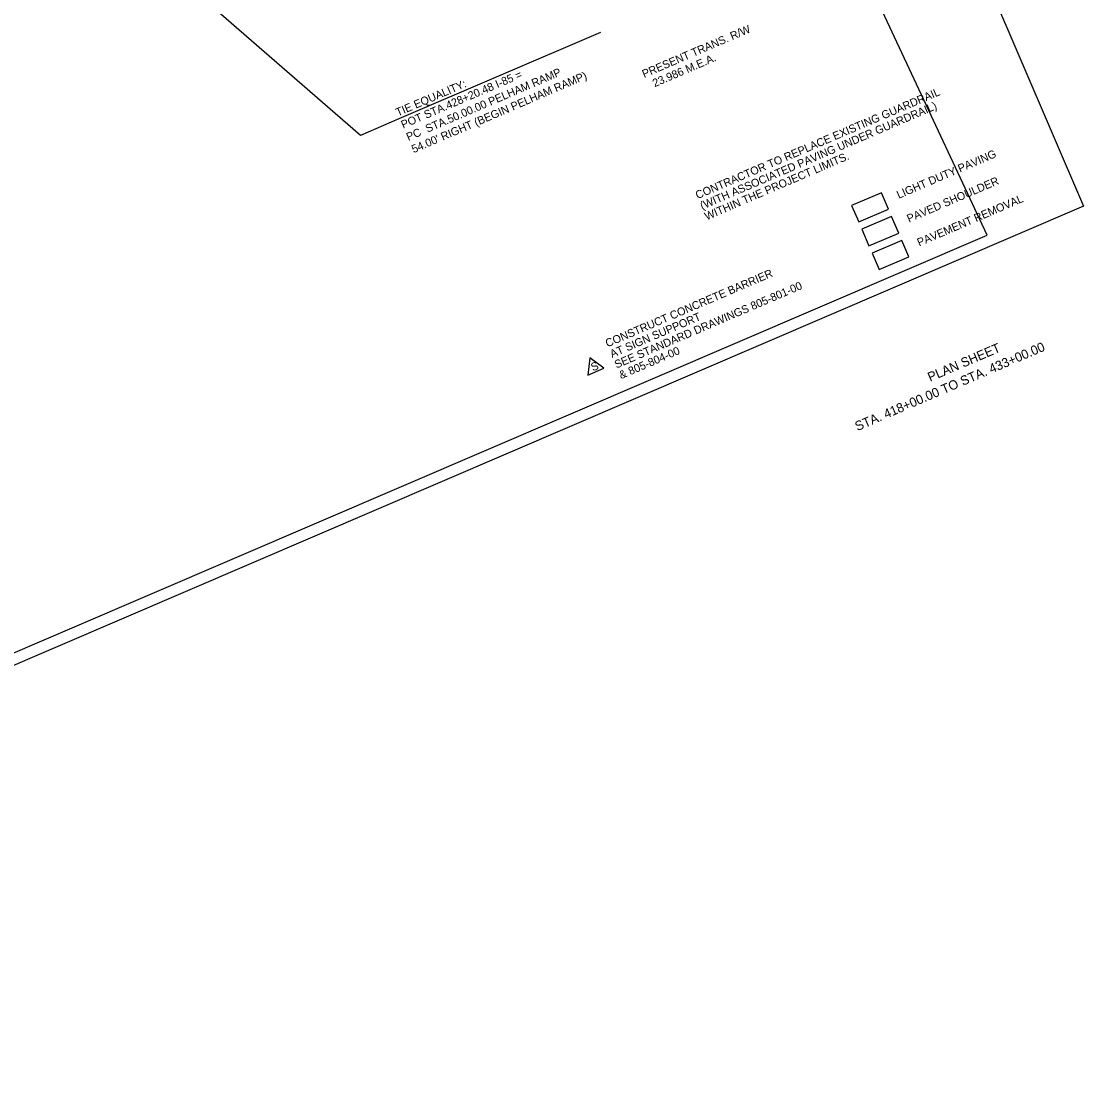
# Model space of a CAD drawing. Extents: x 1619612 to 1621672, y 1101722 to 1103419.
# Drawn here: x 1620732 to 1621528, y 1101745 to 1102544 of the extents above; entities that cross this region are included whole.
import ezdxf

# ---------------------------------------------------------------- set-up
doc = ezdxf.new("R2010")
doc.units = 0
for name, color, linetype in [('RD_EX_BldgApp', 7, 'Continuous'), ('RD_EX_DV_TX_Gov', 7, 'Continuous'), ('RD_EX_Fence_Other', 7, 'Continuous'), ('RD_EX_Misc_Golf_Teebox', 7, 'Continuous'), ('RD_EX_RailRoad', 7, 'Continuous')]:
    doc.layers.add(name, color=color, linetype=linetype)

msp = doc.modelspace()

# ---------------------------------------------------------------- linework, layer by layer
at = {"layer": 'RD_EX_Fence_Other'}
msp.add_lwpolyline([(1619611.56, 1102624.27), (1621150.78, 1103284.88), (1621528.02, 1102405.92), (1619988.8, 1101745.3)], close=True, dxfattribs=at)
at = {"layer": 'RD_EX_Misc_Golf_Teebox'}
msp.add_line((1621166.1, 1102536.16), (1621014.93, 1102471.29), dxfattribs=at)
for points in [[(1621014.93, 1102471.29), (1620986.07, 1102458.9), (1620851.43, 1102576.39)], [(1621359.49, 1102394.07), (1621381.79, 1102403.64), (1621376.49, 1102416), (1621354.19, 1102406.43), (1621359.49, 1102394.07)], [(1621367.16, 1102376.21), (1621389.46, 1102385.78), (1621384.15, 1102398.14), (1621361.85, 1102388.57), (1621367.16, 1102376.21)], [(1621374.82, 1102358.35), (1621397.12, 1102367.92), (1621391.82, 1102380.29), (1621369.52, 1102370.71), (1621374.82, 1102358.35)]]:
    msp.add_lwpolyline(points, dxfattribs=at)
for points in [[(1621359.49, 1102394.07), (1621381.79, 1102403.64), (1621376.49, 1102416), (1621354.19, 1102406.43)], [(1621367.16, 1102376.21), (1621389.46, 1102385.78), (1621384.15, 1102398.14), (1621361.85, 1102388.57)], [(1621374.82, 1102358.35), (1621397.12, 1102367.92), (1621391.82, 1102380.29), (1621369.52, 1102370.71)], [(1621157.99, 1102292.29), (1621156.45, 1102279.36), (1621168.42, 1102284.49)]]:
    msp.add_lwpolyline(points, close=True, dxfattribs=at)
at = {"layer": 'RD_EX_RailRoad'}
msp.add_lwpolyline([(1620011.01, 1101947.11), (1619998.11, 1101917.63), (1620027.5, 1101908.69), (1620077.33, 1101792.57), (1621455.74, 1102384.16), (1621344.3, 1102622.52), (1621323.62, 1102755.47), (1621298.88, 1102749.66), (1621097.02, 1103220), (1620951.48, 1103157.13), (1620938.43, 1103188.78), (1619705.25, 1102659.52)], close=True, dxfattribs=at)
msp.add_lwpolyline([(1620011.01, 1101947.11), (1619998.11, 1101917.63), (1620027.5, 1101908.69), (1620077.33, 1101792.57), (1621455.74, 1102384.16), (1621344.3, 1102622.52), (1621323.62, 1102755.47), (1621298.88, 1102749.66), (1621097.02, 1103220), (1620951.48, 1103157.13), (1620938.43, 1103188.78), (1619705.25, 1102659.52)], close=True, dxfattribs=at)

# ---------------------------------------------------------------- texts
at = {"layer": 'RD_EX_BldgApp'}
for s, p in [('PRESENT TRANS. R/W ', (1621198.71, 1102501.97)), ('  23.986 M.E.A.', (1621202.45, 1102493.24))]:
    msp.add_text(s, height=6, rotation=23.22835, dxfattribs=at).set_placement(p)
at = {"layer": 'RD_EX_DV_TX_Gov'}
for s, height, p in [('STA. 418+00.00 TO STA. 433+00.00', 6.9833, (1621358.48, 1102237.32)), ('PLAN SHEET', 6.983, (1621412.98, 1102274.23))]:
    msp.add_text(s, height=height, rotation=23.22835, dxfattribs=at).set_placement(p)
at = {"layer": 'RD_EX_Misc_Golf_Teebox'}
for s, rotation, p in [('PC  STA.50.00.00 PELHAM RAMP', 23.22672, (1621022.03, 1102454.75)), ('TIE EQUALITY:', 23.22672, (1621014.14, 1102473.13)), ('POT STA.428+20.48 I-85 =', 23.22672, (1621018.09, 1102463.94)), ("54.00' RIGHT (BEGIN PELHAM RAMP)", 23.22672, (1621025.98, 1102445.56)), ('CONTRACTOR TO REPLACE EXISTING GUARDRAIL', 23.22835, (1621238.73, 1102411.1)), ('(WITH ASSOCIATED PAVING UNDER GUARDRAIL)', 23.22835, (1621242.14, 1102403.16)), ('WITHIN THE PROJECT LIMITS.', 23.22835, (1621245.55, 1102395.21)), ('LIGHT DUTY PAVING', 23.22835, (1621389.46, 1102411.36)), ('PAVED SHOULDER', 23.22835, (1621397.12, 1102393.5)), ('PAVEMENT REMOVAL', 23.22835, (1621404.79, 1102375.64)), ('CONSTRUCT CONCRETE BARRIER ', 23.22835, (1621171.19, 1102300.05)), ('SEE STANDARD DRAWINGS 805-801-00', 23.22835, (1621178.01, 1102284.16)), ('AT SIGN SUPPORT', 23.22835, (1621174.6, 1102292.11)), ('& 805-804-00', 23.22835, (1621181.42, 1102276.22)), ('S', 23.22835, (1621160.31, 1102282.1))]:
    msp.add_text(s, height=6, rotation=rotation, dxfattribs=at).set_placement(p)

doc.saveas('drawing.dxf')
